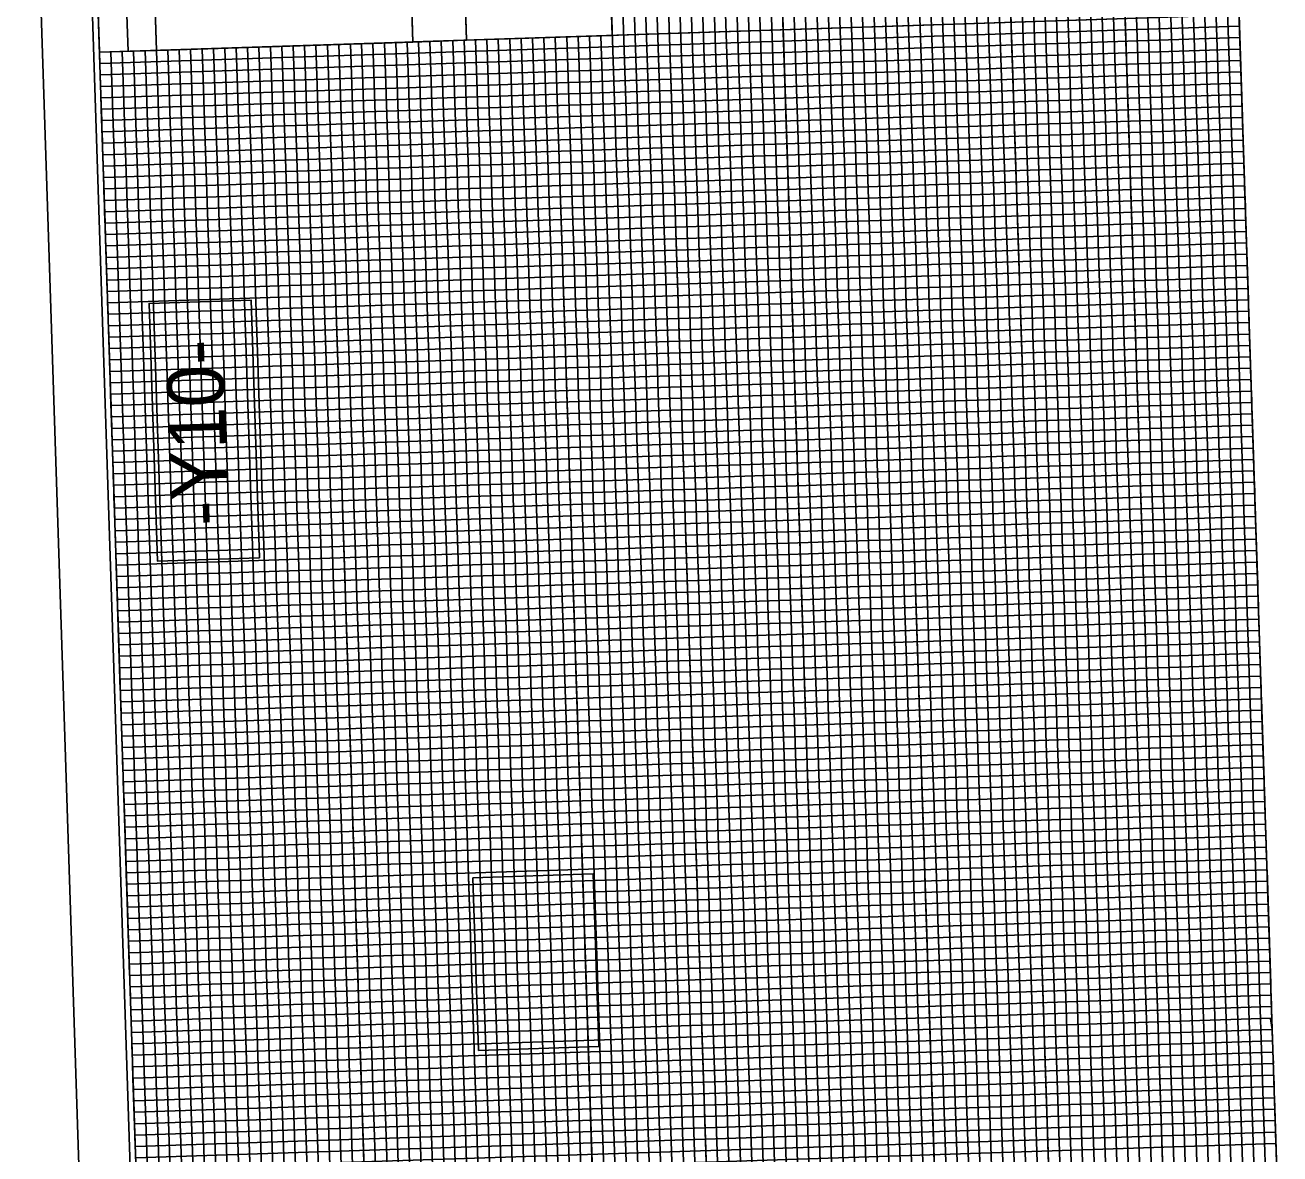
# Model space of a CAD drawing. Extents: x 1627314 to 1628469, y 762309 to 764253.
# Drawn here: x 1627314 to 1627864, y 763293 to 763788 of the extents above; entities that cross this region are included whole.
import ezdxf

# ---------------------------------------------------------------- set-up
doc = ezdxf.new("R2010")
doc.units = 0
for name, color, linetype in [('Old_Level_58', 7, 'Continuous'), ('Prop Grid Mask', 7, 'Continuous'), ('Sheet Data Field CELL', 7, 'Continuous'), ('Sheet DOT Grid CELL', 7, 'Continuous'), ('Sheet Layout Profile Border Port 1', 7, 'Continuous'), ('Sheet Plot Border Inside CELL', 7, 'Continuous'), ('Sheet Plot Border Outside CELL', 7, 'Continuous'), ('Sheet Profile CELL', 7, 'Continuous'), ('Sheet Profile Grid Major CELL', 7, 'Continuous'), ('Sheet Profile Grid Middle CELL', 7, 'Continuous'), ('Sheet Profile Grid Minor CELL', 7, 'Continuous'), ('Sheet Sticker Exception Certification CELL', 7, 'Continuous')]:
    doc.layers.add(name, color=color, linetype=linetype)

msp = doc.modelspace()

# ---------------------------------------------------------------- linework, layer by layer
at = {"layer": 'Old_Level_58'}
msp.add_lwpolyline([(1627507.79, 763781.61), (1627501.25, 763981.49), (1627565.16, 763983.58), (1627571.7, 763783.7)], close=True, dxfattribs=at)
at = {"layer": 'Prop Grid Mask'}
for points in [[(1627417.01, 763554.6), (1627413.31, 763667.62), (1627368.59, 763666.16), (1627372.29, 763553.14)], [(1627513.04, 763338.73), (1627510.57, 763414.35), (1627563.39, 763416.08), (1627565.86, 763340.46)]]:
    msp.add_lwpolyline(points, close=True, dxfattribs=at)
at = {"layer": 'Sheet DOT Grid CELL'}
for p, q in [((1627690.1, 763987.68), (1627739.13, 762488.48)), ((1627740.07, 763989.32), (1627789.11, 762490.12)), ((1627790.04, 763990.95), (1627839.08, 762491.75)), ((1627590.15, 763984.41), (1627639.19, 762485.21)), ((1627640.12, 763986.05), (1627689.16, 762486.85)), ((1627846.55, 763792.69), (1627484.3, 763780.84)), ((1627446.77, 763779.57), (1627489.27, 762480.31)), ((1627496.74, 763781.25), (1627539.24, 762481.95)), ((1627546.72, 763782.83), (1627589.21, 762483.58)), ((1627396.8, 763777.93), (1627439.29, 762478.68)), ((1627848.19, 763742.72), (1627348.46, 763726.37)), ((1627849.82, 763692.75), (1627350.09, 763676.4)), ((1627851.46, 763642.77), (1627351.73, 763626.43)), ((1627853.09, 763592.8), (1627353.36, 763576.45)), ((1627854.73, 763542.83), (1627354.99, 763526.48)), ((1627856.36, 763492.85), (1627356.63, 763476.51)), ((1627858, 763442.88), (1627358.26, 763426.53)), ((1627859.63, 763392.91), (1627359.9, 763376.56)), ((1627861.27, 763342.93), (1627361.53, 763326.59))]:
    msp.add_line(p, q, dxfattribs=at)
at = {"layer": 'Sheet Layout Profile Border Port 1'}
msp.add_lwpolyline([(1627548.65, 762532.28), (1627887.42, 762543.36), (1627841.65, 763942.61), (1627566.8, 763933.62)], dxfattribs=at)
at = {"layer": 'Sheet Plot Border Inside CELL'}
msp.add_lwpolyline([(1628446.34, 762357.53), (1628391.86, 764023.14), (1627337.33, 763988.65), (1627391.81, 762323.04)], close=True, dxfattribs=at)
at = {"layer": 'Sheet Plot Border Outside CELL'}
msp.add_lwpolyline([(1628469.21, 762345.27), (1628413.63, 764044.37), (1627314.22, 764008.4), (1627369.79, 762309.31)], close=True, dxfattribs=at)
at = {"layer": 'Sheet Profile CELL'}
for p, q in [((1627889.05, 762493.39), (1627840.02, 763992.59)), ((1627359.37, 763776.71), (1627352.83, 763976.65))]:
    msp.add_line(p, q, dxfattribs=at)
for points in [[(1627340.28, 763976.24), (1627389.32, 762477.04), (1628438.76, 762511.37), (1628389.72, 764010.57)], [(1627346.82, 763776.3), (1627340.28, 763976.24), (1627365.32, 763977.06), (1627371.86, 763777.12)], [(1627371.86, 763777.12), (1627368.59, 763877.11), (1627481.03, 763880.79), (1627484.3, 763780.79)]]:
    msp.add_lwpolyline(points, close=True, dxfattribs=at)
at = {"layer": 'Sheet Profile Grid Major CELL'}
for points in [[(1627640.12, 763986.05), (1627689.16, 762486.85), (1627739.13, 762488.48), (1627690.1, 763987.68)], [(1627740.07, 763989.32), (1627789.11, 762490.12), (1627789.11, 762490.12), (1627839.08, 762491.75), (1627790.04, 763990.95)], [(1627546.71, 763782.88), (1627589.21, 762483.58), (1627639.19, 762485.21), (1627590.15, 763984.41)], [(1627363.17, 763276.61), (1627361.53, 763326.59), (1627861.27, 763342.93), (1627859.63, 763392.91), (1627359.9, 763376.56), (1627358.26, 763426.53), (1627858, 763442.88), (1627856.36, 763492.85), (1627356.63, 763476.51), (1627354.99, 763526.48), (1627854.73, 763542.83), (1627853.09, 763592.8), (1627353.36, 763576.45), (1627351.73, 763626.43), (1627851.46, 763642.77), (1627849.82, 763692.75), (1627350.09, 763676.4), (1627348.46, 763726.37), (1627848.19, 763742.72), (1627846.55, 763792.69), (1627346.82, 763776.35), (1627345.96, 763802.63)], [(1627439.29, 762478.68), (1627396.79, 763777.98)], [(1627446.77, 763779.62), (1627489.27, 762480.31), (1627539.24, 762481.95), (1627496.74, 763781.25)]]:
    msp.add_lwpolyline(points, dxfattribs=at)
at = {"layer": 'Sheet Profile Grid Middle CELL'}
msp.add_line((1627414.31, 762477.86), (1627371.81, 763777.11), dxfattribs=at)
for points in [[(1627715.08, 763988.5), (1627764.12, 762489.3), (1627814.09, 762490.94), (1627765.06, 763990.13)], [(1627815.03, 763991.77), (1627864.07, 762492.57)], [(1627615.14, 763985.23), (1627664.17, 762486.03), (1627714.15, 762487.67), (1627665.11, 763986.86)], [(1627863.72, 763267.97), (1627862.08, 763317.95), (1627362.35, 763301.6), (1627360.72, 763351.57), (1627860.45, 763367.92), (1627858.81, 763417.89), (1627359.08, 763401.55), (1627357.45, 763451.52), (1627857.18, 763467.87), (1627855.54, 763517.84), (1627355.81, 763501.49), (1627354.18, 763551.47), (1627853.91, 763567.81), (1627852.28, 763617.79), (1627352.54, 763601.44), (1627350.91, 763651.41), (1627850.64, 763667.76), (1627849.01, 763717.73), (1627349.27, 763701.39), (1627347.64, 763751.36), (1627847.37, 763767.71), (1627845.74, 763817.68), (1627570.88, 763808.69)], [(1627521.73, 763782.02), (1627564.23, 762482.76), (1627614.2, 762484.4), (1627570.88, 763808.69)], [(1627421.78, 763778.8), (1627464.28, 762479.49), (1627514.25, 762481.13), (1627471.75, 763780.43)]]:
    msp.add_lwpolyline(points, dxfattribs=at)
at = {"layer": 'Sheet Profile Grid Minor CELL'}
for p, q in [((1627742.5, 762538.62), (1627696.73, 763937.87)), ((1627701.73, 763938.04), (1627747.49, 762538.78)), ((1627752.49, 762538.95), (1627706.72, 763938.2)), ((1627711.72, 763938.36), (1627757.49, 762539.11)), ((1627767.48, 762539.44), (1627721.71, 763938.69)), ((1627726.71, 763938.85), (1627772.48, 762539.6)), ((1627731.71, 763939.02), (1627777.48, 762539.76)), ((1627736.71, 763939.18), (1627782.48, 762539.93)), ((1627792.47, 762540.25), (1627746.7, 763939.51)), ((1627751.7, 763939.67), (1627797.47, 762540.42)), ((1627802.47, 762540.58), (1627756.7, 763939.83)), ((1627761.69, 763940), (1627807.46, 762540.75)), ((1627817.46, 762541.07), (1627771.69, 763940.32)), ((1627776.69, 763940.49), (1627822.45, 762541.24)), ((1627827.45, 762541.4), (1627781.68, 763940.65)), ((1627786.68, 763940.81), (1627832.45, 762541.56)), ((1627842.44, 762541.89), (1627796.67, 763941.14)), ((1627801.67, 763941.3), (1627847.44, 762542.05)), ((1627852.44, 762542.22), (1627806.67, 763941.47)), ((1627811.67, 763941.63), (1627857.44, 762542.38)), ((1627867.43, 762542.71), (1627821.66, 763941.96)), ((1627826.66, 763942.12), (1627872.43, 762542.87)), ((1627877.42, 762543.03), (1627831.66, 763942.29)), ((1627576.79, 763933.95), (1627622.56, 762534.7)), ((1627627.56, 762534.86), (1627581.79, 763934.11)), ((1627586.79, 763934.28), (1627632.56, 762535.02)), ((1627642.55, 762535.35), (1627596.78, 763934.6)), ((1627601.78, 763934.77), (1627647.55, 762535.51)), ((1627652.55, 762535.68), (1627606.78, 763934.93)), ((1627611.77, 763935.09), (1627657.54, 762535.84)), ((1627667.54, 762536.17), (1627621.77, 763935.42)), ((1627626.77, 763935.58), (1627672.53, 762536.33)), ((1627677.53, 762536.5), (1627631.76, 763935.75)), ((1627636.76, 763935.91), (1627682.53, 762536.66)), ((1627692.52, 762536.99), (1627646.75, 763936.24)), ((1627651.75, 763936.4), (1627697.52, 762537.15)), ((1627702.52, 762537.31), (1627656.75, 763936.56)), ((1627661.75, 763936.73), (1627707.52, 762537.48)), ((1627717.51, 762537.8), (1627671.74, 763937.05)), ((1627676.74, 763937.22), (1627722.51, 762537.97)), ((1627727.51, 762538.13), (1627681.74, 763937.38)), ((1627686.73, 763937.55), (1627732.5, 762538.29)), ((1627481.75, 763780.71), (1627522.61, 762531.43)), ((1627486.75, 763780.92), (1627527.61, 762531.59)), ((1627491.74, 763781.09), (1627532.61, 762531.75)), ((1627542.6, 762532.08), (1627501.74, 763781.41)), ((1627506.74, 763781.58), (1627547.6, 762532.25)), ((1627552.6, 762532.41), (1627511.73, 763781.69)), ((1627531.72, 763782.34), (1627572.59, 762533.06)), ((1627577.59, 762533.23), (1627536.72, 763782.51)), ((1627556.71, 763783.16), (1627597.57, 762533.88)), ((1627602.57, 762534.04), (1627561.71, 763783.33)), ((1627392.68, 762527.18), (1627351.82, 763776.51)), ((1627356.82, 763776.67), (1627398.03, 762527.35)), ((1627402.68, 762527.5), (1627361.81, 763776.84))]:
    msp.add_line(p, q, dxfattribs=at)
for points in [[(1627836.65, 763942.45), (1627882.42, 762543.2)], [(1627566.71, 763783.49), (1627607.57, 762534.21), (1627617.56, 762534.53), (1627571.79, 763933.79)], [(1627850.15, 763682.75), (1627849.99, 763687.75), (1627350.25, 763671.4), (1627349.93, 763681.4), (1627849.66, 763697.74), (1627849.5, 763702.74), (1627349.76, 763686.39), (1627349.6, 763691.39), (1627849.33, 763707.74), (1627849.17, 763712.74), (1627349.44, 763696.39), (1627349.11, 763706.38), (1627848.84, 763722.73), (1627848.68, 763727.73), (1627348.95, 763711.38), (1627348.78, 763716.38), (1627848.52, 763732.72), (1627848.35, 763737.72), (1627348.62, 763721.38), (1627348.29, 763731.37), (1627848.03, 763747.72), (1627847.86, 763752.71), (1627348.13, 763736.37), (1627347.97, 763741.37), (1627847.7, 763757.71), (1627847.53, 763762.71), (1627347.8, 763746.36), (1627347.48, 763756.36), (1627847.21, 763772.7), (1627847.04, 763777.7), (1627347.31, 763761.35), (1627347.15, 763766.35), (1627846.88, 763782.7), (1627846.72, 763787.7), (1627346.98, 763771.35), (1627346.66, 763781.34)], [(1627391.8, 763777.82), (1627432.66, 762528.49), (1627442.66, 762528.81), (1627401.79, 763778.14)], [(1627406.79, 763778.31), (1627447.65, 762528.98), (1627452.65, 762529.14), (1627411.79, 763778.47)], [(1627416.78, 763778.63), (1627457.65, 762529.3), (1627467.64, 762529.63), (1627426.78, 763778.96)], [(1627431.78, 763779.13), (1627472.64, 762529.79), (1627477.64, 762529.96), (1627436.77, 763779.29)], [(1627441.77, 763779.45), (1627482.64, 762530.12), (1627492.63, 762530.45), (1627451.77, 763779.78)], [(1627456.86, 763779.95), (1627497.72, 762530.71), (1627502.62, 762530.87), (1627461.76, 763780.11)], [(1627466.76, 763780.27), (1627507.62, 762530.94), (1627517.62, 762531.26), (1627476.75, 763780.6)], [(1627516.73, 763781.85), (1627557.6, 762532.57), (1627567.59, 762532.9), (1627526.73, 763782.18)], [(1627541.72, 763782.67), (1627582.58, 762533.39), (1627592.58, 762533.72), (1627551.71, 763783)], [(1627366.81, 763777), (1627407.68, 762527.67), (1627417.67, 762528), (1627376.81, 763777.33)], [(1627381.8, 763777.44), (1627422.67, 762528.16), (1627427.67, 762528.32), (1627386.8, 763777.65)], [(1627860.12, 763377.91), (1627360.39, 763361.57), (1627360.23, 763366.57), (1627859.96, 763382.91), (1627859.79, 763387.91), (1627360.06, 763371.56), (1627359.73, 763381.56), (1627859.47, 763397.9), (1627859.3, 763402.9), (1627359.57, 763386.55), (1627359.41, 763391.55), (1627859.14, 763407.9), (1627858.98, 763412.9), (1627359.24, 763396.55), (1627358.92, 763406.54), (1627858.65, 763422.89), (1627858.49, 763427.89), (1627358.75, 763411.54), (1627358.59, 763416.54), (1627858.32, 763432.88), (1627858.16, 763437.88), (1627358.43, 763421.54), (1627358.1, 763431.53), (1627857.83, 763447.88), (1627857.67, 763452.87), (1627357.94, 763436.53), (1627357.77, 763441.53), (1627857.51, 763457.87), (1627857.34, 763462.87), (1627357.61, 763446.52), (1627357.28, 763456.52), (1627857.02, 763472.86), (1627856.85, 763477.86), (1627357.12, 763461.51), (1627356.96, 763466.51), (1627856.69, 763482.86), (1627856.53, 763487.86), (1627356.79, 763471.51), (1627356.47, 763481.5), (1627856.2, 763497.85), (1627856.03, 763502.85), (1627356.3, 763486.5), (1627356.14, 763491.5), (1627855.87, 763507.84), (1627855.71, 763512.84), (1627355.98, 763496.5), (1627355.65, 763506.49), (1627855.38, 763522.84), (1627855.22, 763527.83), (1627355.48, 763511.49), (1627355.32, 763516.49), (1627855.05, 763532.83), (1627854.89, 763537.83), (1627355.16, 763521.48), (1627354.83, 763531.48), (1627854.56, 763547.82), (1627854.4, 763552.82), (1627354.67, 763536.47), (1627354.5, 763541.47), (1627854.24, 763557.82), (1627854.07, 763562.82), (1627354.34, 763546.47), (1627354.01, 763556.46), (1627853.75, 763572.81), (1627853.58, 763577.81), (1627353.85, 763561.46), (1627353.69, 763566.46), (1627853.42, 763582.8), (1627853.26, 763587.8), (1627353.52, 763571.46), (1627353.2, 763581.45), (1627852.93, 763597.8), (1627852.77, 763602.79), (1627353.03, 763586.45), (1627352.87, 763591.45), (1627852.6, 763607.79), (1627852.44, 763612.79), (1627352.71, 763596.44), (1627352.38, 763606.44), (1627852.11, 763622.78), (1627851.95, 763627.78), (1627352.22, 763611.43), (1627352.05, 763616.43), (1627851.78, 763632.78), (1627851.62, 763637.78), (1627351.89, 763621.43), (1627351.56, 763631.42), (1627851.29, 763647.77), (1627851.13, 763652.77), (1627351.4, 763636.42), (1627351.23, 763641.42), (1627850.97, 763657.76), (1627850.8, 763662.76), (1627351.07, 763646.42), (1627350.74, 763656.41), (1627850.48, 763672.76), (1627850.31, 763677.75), (1627350.58, 763661.41), (1627350.42, 763666.41), (1627850.15, 763682.75)], [(1627362.68, 763291.61), (1627862.41, 763307.95), (1627862.25, 763312.95), (1627362.51, 763296.6), (1627362.19, 763306.6), (1627861.92, 763322.94), (1627861.76, 763327.94), (1627362.02, 763311.59), (1627361.86, 763316.59), (1627861.59, 763332.94), (1627861.43, 763337.94), (1627361.7, 763321.59), (1627361.37, 763331.58), (1627861.1, 763347.93), (1627860.4, 763352.61), (1627860.94, 763352.93), (1627361.21, 763336.58), (1627361.04, 763341.58), (1627860.78, 763357.93), (1627860.61, 763362.92), (1627360.88, 763346.58), (1627360.55, 763356.57), (1627860.28, 763372.92), (1627860.12, 763377.91)], [(1627363, 763281.61), (1627862.74, 763297.96), (1627862.57, 763302.95), (1627362.84, 763286.61)]]:
    msp.add_lwpolyline(points, dxfattribs=at)
at = {"layer": 'Sheet Sticker Exception Certification CELL'}
for p, q in [((1627484.3, 763780.79), (1627477.76, 763980.72)), ((1627484.3, 763780.79), (1627477.76, 763980.72)), ((1627501.25, 763981.49), (1627507.79, 763781.56)), ((1627501.25, 763981.49), (1627507.79, 763781.56)), ((1627507.79, 763781.56), (1627484.3, 763780.79)), ((1627507.79, 763781.56), (1627484.3, 763780.79))]:
    msp.add_line(p, q, dxfattribs=at)

# ---------------------------------------------------------------- texts
at = {"layer": 'Sheet Data Field CELL'}
msp.add_text('-Y10-', height=25, rotation=91.8735, dxfattribs=at).set_placement((1627403.48, 763569))

doc.saveas('drawing.dxf')
